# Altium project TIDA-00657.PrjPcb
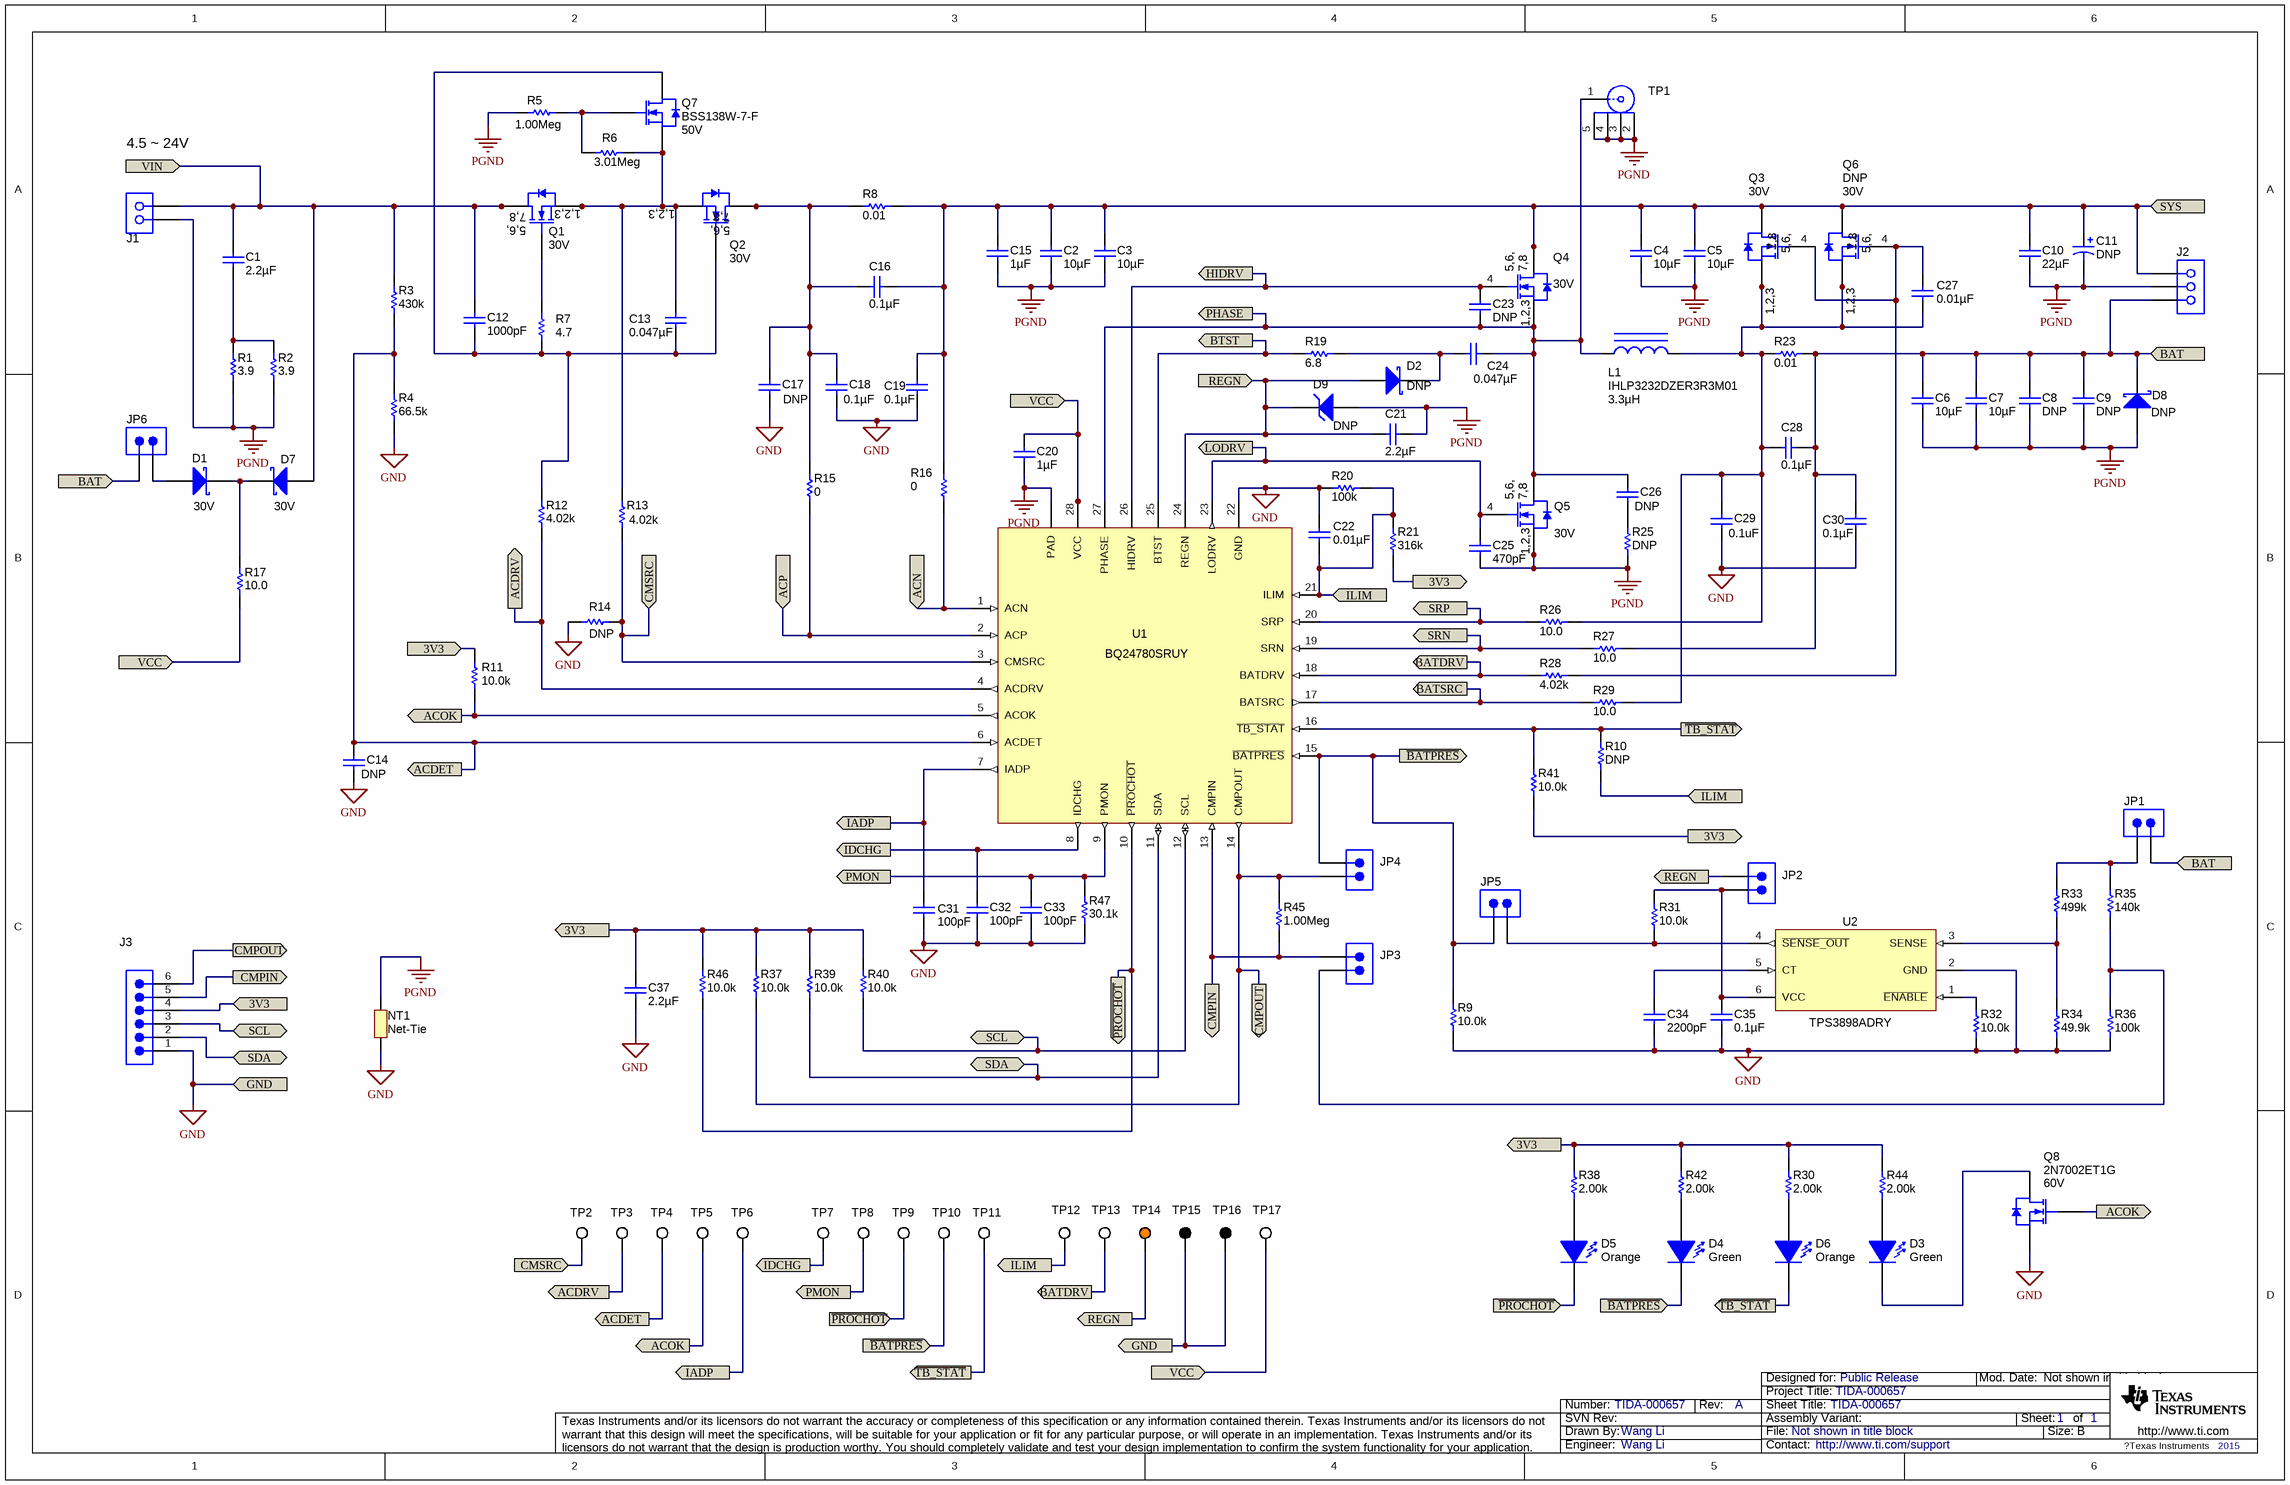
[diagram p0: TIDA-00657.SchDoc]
TechSupport: http://www.ti.com/support; SCH_Rev: A; PRJ_Title: TIDA-000657; PRJ_Number: TIDA-000657; PRJ_Engineer: Wang Li; PRJ_Customer: Public Release; PCB_Rev: B; PCB_Layout: Wang Li; CopyrightYear: 2015
2 sheets, 150 parts. Net scope: flat (ports and power ports of the same name join across sheets).
Board file: TIDA-00657.PcbDoc
Sheets:
  TIDA-00657.SchDoc
  TIDA-00657 Hardware_ANSI-B.SchDoc

## Sheet TIDA-00657.SchDoc: TIDA-000657
size 431 x 279 mm; Date: Not shown in title block; ApprovedBy: Not shown in title block; CheckedBy: Not shown in title block; Author: Not shown in title block; CompanyName: Not shown in title block; DrawnBy: Wang Li; Engineer: Wang Li; Organization: Not shown in title block; Address1: Not shown in title block; Address2: Not shown in title block; Address3: Not shown in title block; Address4: Not shown in title block; DocumentNumber: 1; Revision: A; SheetNumber: 1; SheetTotal: 1; PageSetup: Record=PageOptions¦CenterHorizontal=True¦CenterVertical=True¦PrintScale=0.62¦XCorrection=1.00¦YCorrection=1.00¦PrintKind=0¦BorderSize=5000000¦LeftOffset=0¦BottomOffset=0¦Orientation=2¦PaperLength=1000¦PaperWidth=1000¦Scale=100¦PaperSource=15¦PrintQuality=-3¦MediaType=1¦DitherType=10¦PrintScaleMode=1¦PaperKind=Letter¦PaperIndex=1

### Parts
C1  ValueDisplayed: 2.2µF  [1206]  (hidden comment: GRM31MR71E225KA93L)
C2  ValueDisplayed: 10µF  [1206]  (hidden comment: GRM31CR61E106KA12L)
C3  ValueDisplayed: 10µF  [1206]  (hidden comment: GRM31CR61E106KA12L)
C4  ValueDisplayed: 10µF  [1206]  (hidden comment: GRM31CR61E106KA12L)
C5  ValueDisplayed: 10µF  [1206]  (hidden comment: GRM31CR61E106KA12L)
C6  ValueDisplayed: 10µF  [1206]  (hidden comment: GRM31CR61E106KA12L)
C7  ValueDisplayed: 10µF  [1206]  (hidden comment: GRM31CR61E106KA12L)
C8  ValueDisplayed: DNP  [1206]  (hidden comment: GRM31CR61E106KA12L)
C9  ValueDisplayed: DNP  [1206]  (hidden comment: GRM31CR61E106KA12L)
C10  ValueDisplayed: 22µF  [1210]  (hidden comment: GRM32ER61E226KE15L)
C11  ValueDisplayed: DNP  [7343-28]  (hidden comment: 16TQC150MYF)
C12  ValueDisplayed: 1000pF  [0603]  (hidden comment: GRM188R71H102KA01D)
C13  ValueDisplayed: 0.047µF  [0603]  (hidden comment: GRM188R71H473KA61D)
C14  value DNP  [0603]  (hidden comment: GRM188R71E104KA01D)
C15  ValueDisplayed: 1µF  [0603]  (hidden comment: GRM188R71E105KA12D)
C16  ValueDisplayed: 0.1µF  [0603]  (hidden comment: GRM188R71E104KA01D)
C17  Value1: DNP  [0603]  (hidden comment: GRM188R71E105KA12D)
C18  ValueDisplayed: 0.1µF  [0603]  (hidden comment: GRM188R71E104KA01D)
C19  ValueDisplayed: 0.1µF  [0603]  (hidden comment: GRM188R71E104KA01D)
C20  ValueDisplayed: 1µF  [0603]  (hidden comment: GRM188R71E105KA12D)
C21  ValueDisplayed: 2.2µF  [0603]  (hidden comment: GRM188R61C225KE15D)
C22  ValueDisplayed: 0.01µF  [0603]  (hidden comment: C0603X103K5RACTU)
C23  ValueDisplayed: DNP  [0603]  (hidden comment: GRM188R71E104KA01D)
C24  ValueDisplayed: 0.047µF  [0603]  (hidden comment: GRM188R71H473KA61D)
C25  ValueDisplayed: 470pF  [0603]  (hidden comment: GRM188R71H471KA01D)
C26  value DNP  [0603]  (hidden comment: GRM188R71E104KA01D)
C27  ValueDisplayed: 0.01µF  [0603]  (hidden comment: C0603X103K5RACTU)
C28  ValueDisplayed: 0.1µF  [0603]  (hidden comment: GRM188R71E104KA01D)
C29  value 0.1uF  [0603]  (hidden comment: GRM188R71E104KA01D)
C30  ValueDisplayed: 0.1µF  [0603]  (hidden comment: GRM188R71E104KA01D)
C31  ValueDisplayed: 100pF  [0603]  (hidden comment: C0603C101J5GAC)
C32  ValueDisplayed: 100pF  [0603]  (hidden comment: C0603C101J5GAC)
C33  ValueDisplayed: 100pF  [0603]  (hidden comment: C0603C101J5GAC)
C34  ValueDisplayed: 2200pF  [0805_HV]  (hidden comment: C2012C0G1H222J)
C35  ValueDisplayed: 0.1µF  [0603]  (hidden comment: GRM188R71E104KA01D)
C37  ValueDisplayed: 2.2µF  [0603]  (hidden comment: GRM188R71A225KE15D)
D1  value 30V  [sod-323]  (hidden comment: BAT54HT1G)
D2  value DNP  [sod-323]  (hidden comment: BAT54HT1G)
D3  value Green  [LED_LTST-C190]  (hidden comment: LTST-C190GKT)
D4  value Green  [LED_LTST-C190]  (hidden comment: LTST-C190GKT)
D5  value Orange  [LED_LTST-C190]  (hidden comment: LTST-C190KFKT)
D6  value Orange  [LED_LTST-C190]  (hidden comment: LTST-C190KFKT)
D7  value 30V  [sod-323]  (hidden comment: BAT54HT1G)
D8  value DNP  [SMA]  (hidden comment: SS12-E3/61T)
D9  Vz_V: DNP  [SOD-123]  (hidden comment: BZT52C8V2-7-F)
J1  ED120/2DS  [CONN_ED120-2DS]  (value not drawn)
J2  ED120/3DS  [CONN_ED120_3DS]  (value not drawn)
J3  ED555/6DS  [TERM_BLK_ED555-6DS]  (value not drawn)
JP1  5-146261-1  [CONN_5-146261-1]  (value not drawn)
JP2  5-146261-1  [CONN_5-146261-1]  (value not drawn)
JP3  5-146261-1  [CONN_5-146261-1]  (value not drawn)
JP4  5-146261-1  [CONN_5-146261-1]  (value not drawn)
JP5  5-146261-1  [CONN_5-146261-1]  (value not drawn)
JP6  5-146261-1  [CONN_5-146261-1]  (value not drawn)
L1  IHLP3232DZER3R3M01  ValueDisplayed: 3.3µH  [IHLP-3232DZ]
NT1  Net-Tie  [Net-Tie_20milWide_60milLong]  (net tie, no BOM)
Q1  value 30V  [TRANS_NexFET_Q3]  (hidden comment: CSD17308Q3)
Q2  value 30V  [TRANS_NexFET_Q3]  (hidden comment: CSD17308Q3)
Q3  value 30V  [TRANS_NexFET_Q3]  (hidden comment: CSD17308Q3)
Q4  value 30V  [TRANS_NexFET_Q3]  (hidden comment: CSD17308Q3)
Q5  value 30V  [TRANS_NexFET_Q3]  (hidden comment: CSD17308Q3)
Q6  DNP  value 30V  [TRANS_NexFET_Q3]
Q7  BSS138W-7-F  value 50V  [SOT-323]
Q8  2N7002ET1G  value 60V  [SOT-23]
R1  value 3.9  [1210M]  (hidden comment: ERJ-14YJ3R9U)
R2  value 3.9  [1210M]  (hidden comment: ERJ-14YJ3R9U)
R3  value 430k  [0603]  (hidden comment: RC0603FR-07430KL)
R4  value 66.5k  [0603]  (hidden comment: CRCW060366K5FKEA)
R5  value 1.00Meg  [0603]  (hidden comment: CRCW06031M00FKEA)
R6  value 3.01Meg  [0603]  (hidden comment: CRCW06033M01FKEA)
R7  value 4.7  [0603]  (hidden comment: CRCW06034R70JNEA)
R8  value 0.01  [1206]  (hidden comment: WSLP1206R0100FEA)
R9  value 10.0k  [0603]  (hidden comment: CRCW060310K0FKEA)
R10  value DNP  [0603]  (hidden comment: RG1608P-8452-B-T5)
R11  value 10.0k  [0603]  (hidden comment: CRCW060310K0FKEA)
R12  value 4.02k  [0603]  (hidden comment: CRCW06034K02FKEA)
R13  value 4.02k  [0603]  (hidden comment: CRCW06034K02FKEA)
R14  value DNP  [0603]  (hidden comment: CRCW06030000Z0EA)
R15  value 0  [0603]  (hidden comment: CRCW06030000Z0EA)
R16  value 0  [0603]  (hidden comment: CRCW06030000Z0EA)
R17  value 10.0  [1206]  (hidden comment: ERJ-8ENF10R0V)
R19  value 6.8  [0603]  (hidden comment: CRCW06036R80JNEA)
R20  value 100k  [0603]  (hidden comment: CRCW0603100KJNEA)
R21  value 316k  [0603]  (hidden comment: CRCW0603316KFKEA)
R23  value 0.01  [1206]  (hidden comment: WSLP1206R0100FEA)
R25  value DNP  [0603]  (hidden comment: CRCW0603100KFKEA)
R26  value 10.0  [0603]  (hidden comment: RC0603FR-0710RL)
R27  value 10.0  [0603]  (hidden comment: RC0603FR-0710RL)
R28  value 4.02k  [0603]  (hidden comment: CRCW06034K02FKEA)
R29  value 10.0  [0603]  (hidden comment: RC0603FR-0710RL)
R30  value 2.00k  [0603]  (hidden comment: CRCW06032K00FKEA)
R31  value 10.0k  [0603]  (hidden comment: CRCW060310K0FKEA)
R32  value 10.0k  [0603]  (hidden comment: CRCW060310K0FKEA)
R33  value 499k  [0603]  (hidden comment: CRCW0603499KFKEA)
R34  value 49.9k  [0603]  (hidden comment: CRCW060349K9FKEA)
R35  value 140k  [0603]  (hidden comment: CRCW0603140KFKEA)
R36  value 100k  [0603]  (hidden comment: CRCW0603100KJNEA)
R37  value 10.0k  [0603]  (hidden comment: CRCW060310K0FKEA)
R38  value 2.00k  [0603]  (hidden comment: CRCW06032K00FKEA)
R39  value 10.0k  [0603]  (hidden comment: CRCW060310K0FKEA)
R40  value 10.0k  [0603]  (hidden comment: CRCW060310K0FKEA)
R41  value 10.0k  [0603]  (hidden comment: CRCW060310K0FKEA)
R42  value 2.00k  [0603]  (hidden comment: CRCW06032K00FKEA)
R44  value 2.00k  [0603]  (hidden comment: CRCW06032K00FKEA)
R45  value 1.00Meg  [0603]  (hidden comment: CRCW06031M00FKEA)
R46  value 10.0k  [0603]  (hidden comment: CRCW060310K0FKEA)
R47  value 30.1k  [0603]  (hidden comment: CRCW060330K1FKEA)
TP1  131-5031-00  [Tek_131-5031-00]  (value not drawn)
TP2  5002  [Keystone5002]  (value not drawn)
TP3  5002  [Keystone5002]  (value not drawn)
TP4  5002  [Keystone5002]  (value not drawn)
TP5  5002  [Keystone5002]  (value not drawn)
TP6  5002  [Keystone5002]  (value not drawn)
TP7  5002  [Keystone5002]  (value not drawn)
TP8  5002  [Keystone5002]  (value not drawn)
TP9  5002  [Keystone5002]  (value not drawn)
TP10  5002  [Keystone5002]  (value not drawn)
TP11  5002  [Keystone5002]  (value not drawn)
TP12  5002  [Keystone5002]  (value not drawn)
TP13  5002  [Keystone5002]  (value not drawn)
TP14  5003  [Keystone5003]  (value not drawn)
TP15  5001  [Keystone5001]  (value not drawn)
TP16  5001  [Keystone5001]  (value not drawn)
TP17  5002  [Keystone5002]  (value not drawn)
U1  BQ24780SRUY  [RUY0028A]
U2  TPS3898ADRY  [DRY0006A]

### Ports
3V3, 3V3 (in), ACDET, ACDRV (out), ACN (in), ACOK (out), ACP (in), BAT, BATDRV (out), BATSRC (out), BTST, CMPIN, CMPOUT (out), CMSRC, GND, HIDRV, IADP (out), IDCHG (out), ILIM, LODRV (out), PHASE, PMON (out), REGN, SCL (bidir), SDA (bidir), SRN, SRP, SYS, VCC, VIN, ~{BATPRES}, ~{PROCHOT}, ~{TB_STAT} (out)

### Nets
GND: C14.2 C17.2 C18.2 C19.2 C22.1 C29.2 C30.2 C31.2 C32.2 C33.2 C34.1 C35.1 C37.2 J3.1 NT1.1 Q8.2(S) R4.1 R9.2 R14.2 R20.2 R32.2 R34.1 R36.1 R47.2 TP15.1 TP16.1 U1.22(GND) U2.2(GND) ; port GND
PGND: C2.2 C3.2 C4.2 C5.2 C6.2 C7.2 C8.2 C9.2 C10.2 C11.2(-) C15.2 C20.2 C21.2 C25.2 D8.2(A) D9.2(A) J1.2 J2.2 NT1.2 Q5.1(S) Q5.2(S) Q5.3(S) R1.1 R2.1 R5.1 R25.1 TP1.2 TP1.3 TP1.4 TP1.5 U1.29(PAD)
3V3: C37.1 J3.4 R11.2 R21.1 R30.1 R37.2 R38.1 R39.2 R40.1 R41.2 R42.1 R44.1 R46.2 ; port 3V3
~{BATPRES}: D4.2(K) JP4.1 JP5.1 R9.1 TP10.1 U1.15(~{BATPRES}) ; port ~{BATPRES}
~{PROCHOT}: D5.2(K) R46.1 TP9.1 U1.10(~{PROCHOT}) ; port ~{PROCHOT}
~{TB_STAT}: D6.2(K) R10.2 R41.1 TP11.1 U1.16(~{TB_STAT}) ; port ~{TB_STAT}
ACDET: C14.1 R3.1 R4.2 TP4.1 U1.6(ACDET) ; port ACDET
ACDRV: R12.1 TP3.1 U1.4(ACDRV) ; port ACDRV
ACN: R16.1 U1.1(ACN) ; port ACN
ACOK: Q8.1(G) R11.1 TP5.1 U1.5(ACOK) ; port ACOK
ACP: R15.1 U1.2(ACP) ; port ACP
BAT: C6.1 C7.1 C8.1 C9.1 C28.2 C30.1 D8.1(K) J2.1 JP1.1 JP6.2 R23.2 R27.2 ; port BAT
BATDRV: R28.2 TP13.1 U1.18(BATDRV) ; port BATDRV
BATSRC: R29.1 U1.17(BATSRC) ; port BATSRC
BTST: R19.1 U1.25(BTST) ; port BTST
CMPIN: J3.5 JP3.1 R45.1 U1.13(CMPIN) ; port CMPIN
CMPOUT: J3.6 JP4.2 R37.1 R45.2 U1.14(CMPOUT) ; port CMPOUT
CMSRC: R13.1 R14.1 TP2.1 U1.3(CMSRC) ; port CMSRC
HIDRV: C23.1 Q4.4(G) U1.26(HIDRV) ; port HIDRV
IADP: C31.1 TP6.1 U1.7(IADP) ; port IADP
IDCHG: C32.1 TP7.1 U1.8(IDCHG) ; port IDCHG
ILIM: C22.2 R10.1 R20.1 R21.2 TP12.1 U1.21(ILIM) ; port ILIM
LODRV: C25.1 Q5.4(G) U1.23(LODRV) ; port LODRV
PHASE: C23.2 C24.2 C26.1 L1.1 Q4.1(S) Q4.2(S) Q4.3(S) Q5.5(D) Q5.6(D) Q5.7(D) Q5.8(D) TP1.1 U1.27(PHASE) ; port PHASE
PMON: C33.1 R47.1 TP8.1 U1.9(PMON) ; port PMON
REGN: C21.1 D2.2(A) D9.1(K) JP2.1 TP14.1 U1.24(REGN) ; port REGN
SCL: J3.3 R40.2 U1.12(SCL) ; port SCL
SDA: J3.2 R39.1 U1.11(SDA) ; port SDA
SRN: R27.1 U1.19(SRN) ; port SRN
SRP: R26.1 U1.20(SRP) ; port SRP
SYS: C2.1 C3.1 C4.1 C5.1 C10.1 C11.1(+) C15.1 C16.2 C19.1 J2.3 Q3.5(D) Q3.6(D) Q3.7(D) Q3.8(D) Q4.5(D) Q4.6(D) Q4.7(D) Q4.8(D) Q6.5(D) Q6.6(D) Q6.7(D) Q6.8(D) R8.2 R16.2 ; port SYS
VCC: C20.1 R17.1 TP17.1 U1.28(VCC) ; port VCC
VIN: C1.1 C12.1 D7.2(A) J1.1 Q1.5(D) Q1.6(D) Q1.7(D) Q1.8(D) R3.2 ; port VIN
NetC1_2: C1.2 R1.2 R2.2
NetC12_2: C12.2 C13.2 Q2.4(G) Q7.3(D) R7.1 R12.2
NetC13_1: C13.1 Q1.1(S) Q1.2(S) Q1.3(S) Q2.1(S) Q2.2(S) Q2.3(S) Q7.2(S) R6.2 R13.2
NetC16_1: C16.1 C17.1 C18.1 Q2.5(D) Q2.6(D) Q2.7(D) Q2.8(D) R8.1 R15.2
NetC24_1: C24.1 D2.1(K) R19.2
NetC26_2: C26.2 R25.2
NetC27_1: C27.1 Q3.4(G) Q6.4(G) R28.1
NetC27_2: C27.2 C28.1 C29.1 L1.2 Q3.1(S) Q3.2(S) Q3.3(S) Q6.1(S) Q6.2(S) Q6.3(S) R23.1 R26.2 R29.2
NetC34_2: C34.2 U2.5(CT)
NetC35_2: C35.2 JP2.2 R31.1 U2.6(VCC)
NetD1_1: D1.1(K) D7.1(K) R17.2
NetD1_2: D1.2(A) JP6.1
NetD3_1: D3.1(A) R44.2
NetD3_2: D3.2(K) Q8.3(D)
NetD4_1: D4.1(A) R42.2
NetD5_1: D5.1(A) R38.2
NetD6_1: D6.1(A) R30.2
NetJP1_2: JP1.2 R33.2 R35.2
NetJP3_2: JP3.2 R35.1 R36.2
NetJP5_2: JP5.2 R31.2 U2.4(~{SENSE_OUT})
NetQ1_4: Q1.4(G) R7.2
NetQ7_1: Q7.1(G) R5.2 R6.1
NetR32_1: R32.1 U2.1(~{ENABLE})
NetR33_1: R33.1 R34.2 U2.3(SENSE)

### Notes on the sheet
- 4.5 ~ 24V

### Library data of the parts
C1 = GRM31MR71E225KA93L: CAP, CERM, 2.2uF, 25V, +/-10%, X7R, 1206; Manufacturer: MuRata; Polarized: N; CompType: Capacitor; U/M: EA; Cap_F: 0.0000022; Tolerance_%: 10; Value1: Unknown; VDC_V: 25; TaMin_C: -55; TaMax_C: 125; Cap_Case: 1210
C2-C9 = GRM31CR61E106KA12L: CAP, CERM, 10uF, 25V, +/-10%, X5R, 1206; Manufacturer: MuRata; Polarized: N; CompType: Capacitor; U/M: EA; Cap_F: 0.00001; Tolerance_%: 10; ESR_Ohm: 0.004; Value1: 0.004 ohm; VDC_V: 25; TaMin_C: -55; TaMax_C: 85
C10 = GRM32ER61E226KE15L: CAP, CERM, 22uF, 25V, +/-10%, X5R, 1210; Manufacturer: MuRata; Polarized: N; CompType: Capacitor; U/M: EA; Cap_F: 0.000022; Tolerance_%: 10; ESR_Ohm: 0.002; Value1: 0.002 ohm; VDC_V: 25; IRMS_A: 3.67; TaMin_C: -55; TaMax_C: 85
C11 = 16TQC150MYF: CAP, TA, 150uF, 16V, +/-20%, 0.05 ohm, SMD; Manufacturer: Panasonic; Polarized: Y; CompType: Capacitor; U/M: EA; Cap_F: 0.00015; Tolerance_%: 20; VDC_V: 16; ESR_Ohm: 0.05; IRMS_A: 1.8; TaMin_C: -55; TaMax_C: 105; Cap_Case: 7.3x2.8x4.3
C12 = GRM188R71H102KA01D: CAP, CERM, 1000pF, 50V, +/-10%, X7R, 0603; Manufacturer: MuRata; Polarized: N; CompType: Capacitor; U/M: EA; Cap_F: 0.000000001; Tolerance_%: 10; Value1: Unknown; VDC_V: 50; TaMin_C: -55; TaMax_C: 125
C13 C24 = GRM188R71H473KA61D: CAP, CERM, 0.047uF, 50V, +/-10%, X7R, 0603; Manufacturer: MuRata; Polarized: N; CompType: Capacitor; U/M: EA; Cap_F: 0.000000047; Tolerance_%: 10; Value1: Unknown; VDC_V: 50; TaMin_C: -55; TaMax_C: 125
C14 C16 C18 C19 C23 C26 C28-C30 C35 = GRM188R71E104KA01D: CAP, CERM, 0.1uF, 25V, +/-10%, X7R, 0603; Manufacturer: MuRata; Polarized: N; CompType: Capacitor; U/M: EA; Cap_F: 0.0000001; Tolerance_%: 10; Value1: Unknown; VDC_V: 25; TaMin_C: -55; TaMax_C: 125
C15 C20 = GRM188R71E105KA12D: CAP, CERM, 1uF, 25V, +/-10%, X7R, 0603; Manufacturer: MuRata; Polarized: N; CompType: Capacitor; U/M: EA; Cap_F: 0.000001; Tolerance_%: 10; Value1: Unknown; VDC_V: 25; TaMin_C: -55; TaMax_C: 125
C17 = GRM188R71E105KA12D: CAP, CERM, 1uF, 25V, +/-10%, X7R, 0603; Manufacturer: MuRata; Polarized: N; CompType: Capacitor; U/M: EA; Cap_F: 0.000001; Tolerance_%: 10; VDC_V: 25; TaMin_C: -55; TaMax_C: 125
C21 = GRM188R61C225KE15D: CAP, CERM, 2.2uF, 16V, +/-10%, X5R, 0603; Manufacturer: MuRata; Polarized: N; CompType: Capacitor; U/M: EA; Cap_F: 0.0000022; Tolerance_%: 10; Value1: Unknown; VDC_V: 16; TaMin_C: -55; TaMax_C: 85
C22 C27 = C0603X103K5RACTU: CAP, CERM, 0.01uF, 50V, +/-10%, X7R, 0603; Manufacturer: Kemet; Polarized: N; CompType: Capacitor; U/M: EA; Cap_F: 0.00000001; Tolerance_%: 10; Value1: Unknown; VDC_V: 50; TaMin_C: -55; TaMax_C: 125
C25 = GRM188R71H471KA01D: CAP, CERM, 470pF, 50V, +/-10%, X7R, 0603; Manufacturer: MuRata; Polarized: N; CompType: Capacitor; U/M: EA; Cap_F: 0.00000000047; Tolerance_%: 10; Value1: Unknown; VDC_V: 50; TaMin_C: -55; TaMax_C: 125
C31-C33 = C0603C101J5GAC: CAP, CERM, 100pF, 50V, +/-5%, C0G/NP0, 0603; Manufacturer: Kemet; Polarized: N; CompType: Capacitor; U/M: EA; Cap_F: 0.0000000001; Tolerance_%: 5; Value1: Unknown; VDC_V: 50; TaMin_C: -55; TaMax_C: 125
C34 = C2012C0G1H222J: CAP, CERM, 2200pF, 50V, +/-5%, C0G/NP0, 0805; Manufacturer: TDK; Polarized: N; CompType: Capacitor; U/M: EA; Cap_F: 0.0000000022; Tolerance_%: 5; Value1: Unknown; VDC_V: 50; TaMin_C: -55; TaMax_C: 125; Cap_Case: 0805
C37 = GRM188R71A225KE15D: CAP, CERM, 2.2uF, 10V, +/-10%, X7R, 0603; Manufacturer: MuRata; Polarized: N; CompType: Capacitor; U/M: EA; Cap_F: 0.0000022; Tolerance_%: 10; ESR_Ohm: 0.009; Value1: 0.009 ohm; TaMin_C: -55; TaMax_C: 125
D1 D2 D7 = BAT54HT1G: Diode, Schottky, 30V, 0.2A, SOD-323; Manufacturer: ON Semiconductor; U/M: EA; Vf_V: 0.35; Value2: 0.35V; Io_A: 0.2; Vr_V: 30
D3 D4 = LTST-C190GKT: LED, Green, SMD; Manufacturer: Lite-On; Vf_V: 2.1; Value2: 2.1V; Io_A: 0.02; Power_TotalModule: 0.1; Value1: 0.1W; U/M: EA
D5 D6 = LTST-C190KFKT: LED, Orange, SMD; Manufacturer: Lite-On; Type: AlInGaP; Vf_V: 2; Value2: 2V; Io_A: 0.02; Power_TotalModule: 0.075; Value1: 0.075W; U/M: EA
D8 = SS12-E3/61T: Diode, Schottky, 20V, 1A, SMA; Manufacturer: Vishay-Semiconductor; U/M: EA; Vf_V: 0.5; Value2: 0.5V; Io_A: 1; Vr_V: 20; TJmax_C: 125; RJC_CperW: 28
D9 = BZT52C8V2-7-F: Diode, Zener, 8.2V, 500mW, SOD-123; Manufacturer: Diodes Inc.; SymbolCreator: a0412235; U/M: EA; Power_W: 0.5; Value1: 0.5W; RJA_CperW: 338
J1 = ED120/2DS: TERMINAL BLOCK 5.08MM VERT 2POS; Manufacturer: On-Shore Technology, Inc.; U/M: EA
J2 = ED120/3DS: TERMINAL BLOCK 5.08MM VERT 3POS; Manufacturer: On-Shore Technology, Inc.; SymbolCreator: a0412235; U/M: EA
J3 = ED555/6DS: Terminal Block, 6A, 3.5mm Pitch, 6-Pos, TH; Manufacturer: On-Shore Technology, Inc.; SymbolCreator: a0412235; CompType: Connector; U/M: EA
JP1-JP6 = 5-146261-1: Header, 100mil, 2x1, Gold plated, TH; Manufacturer: TE Connectivity; SymbolCreator: a0412235; U/M: EA
L1 = IHLP3232DZER3R3M01: Inductor, Shielded, Powdered Iron, 3.3uH, 9.2A, 17.7 ohm, SMD; Manufacturer: Vishay-Dale; Ind_H: 3.3E-6; Imax_A: 9.2; Irms: 9.2A @ 40C rise; Isat: 20A @ 20% inductance drop; DCR_ohm: 17.7; U/M: EA
NT1 = Net-Tie: Single point connection between nets.; SymbolCreator: codlsc
Q1-Q6 = CSD17308Q3: MOSFET, N-CH, 30V, 47A, SON 3.3x3.3mm; Manufacturer: Texas Instruments; Alternate Manufacturer: None; U/M: EA; ChType: N; VdsMax_V: 30; Value1: 0.0094 ohm; Rdson45_Ohm: 0.0094; Value2: 3.9 nC; QgTyp_nC: 3.9; Vgs_V: 10; IdsMax_A: 47
Q7 = BSS138W-7-F: MOSFET, N-CH, 50V, 0.2A, SOT-323; Manufacturer: Diodes Inc.; Alternate Manufacturer: None; U/M: EA; ChType: N; VdsMax_V: 50; Value1: 3.5 ohm; Rdson45_Ohm: 3.5; Value2: ? nC; Vgs_V: 1.5; IdsMax_A: 0.2
Q8 = 2N7002ET1G: MOSFET, N-CH, 60V, 0.26A, SOT-23; Manufacturer: ON Semiconductor; Alternate Manufacturer: None; U/M: EA; ChType: N; VdsMax_V: 60; Value1: 3 ohm; Rdson45_Ohm: 3; Value2: 0.81 nC; QgTyp_nC: 0.81; Vgs_V: 20; IdsMax_A: 0.26
R1 R2 = ERJ-14YJ3R9U: RES, 3.9 ohm, 5%, 0.5W, 1210; Manufacturer: Panasonic; CompType: Resistor; Value_Code: 3R90; Tolerance_%: 5; Power_W: 0.5; VDC_V: 200; TempCo: 600 ppm/C; EIA_Code: E24; U/M: EA
R3 = RC0603FR-07430KL: RES, 430k ohm, 1%, 0.1W, 0603; Manufacturer: Yageo America; CompType: Resistor; Res_ohm: 430000; Tolerance_%: 1; Power_W: 0.1; VDC_V: 150; TempCo: 200 ppm/C; U/M: EA
R4 = CRCW060366K5FKEA: RES, 66.5k ohm, 1%, 0.1W, 0603; Manufacturer: Vishay-Dale; CompType: Resistor; Res_ohm: 66500; Value_Code: 66k5; Tolerance_%: 1; Power_W: 0.1; VDC_V: 75; TempCo: 100 ppm/C; EIA_Code: E96; U/M: EA
R5 R45 = CRCW06031M00FKEA: RES, 1.00Meg ohm, 1%, 0.1W, 0603; Manufacturer: Vishay-Dale; CompType: Resistor; Res_ohm: 1000000; Value_Code: 1M00; Tolerance_%: 1; Power_W: 0.1; VDC_V: 75; TempCo: 100 ppm/C; EIA_Code: E96; U/M: EA
R6 = CRCW06033M01FKEA: RES, 3.01Meg ohm, 1%, 0.1W, 0603; Manufacturer: Vishay-Dale; CompType: Resistor; Res_ohm: 3010000; Value_Code: 3M01; Tolerance_%: 1; Power_W: 0.1; VDC_V: 75; TempCo: 100 ppm/C; EIA_Code: E96; U/M: EA
R7 = CRCW06034R70JNEA: RES, 4.7 ohm, 5%, 0.1W, 0603; Manufacturer: Vishay-Dale; CompType: Resistor; Value_Code: 4R70; Tolerance_%: 5; Power_W: 0.1; VDC_V: 75; TempCo: 200 ppm/C; EIA_Code: E24; U/M: EA
R8 R23 = WSLP1206R0100FEA: RES, 0.01 ohm, 1%, 1W, 1206; Manufacturer: Vishay-Dale; CompType: Resistor; Value_Code: R010; Tolerance_%: 1; TempCo: 75 ppm/C; EIA_Code: E96; U/M: EA
R9 R11 R31 R32 R37 R39-R41 R46 = CRCW060310K0FKEA: RES, 10.0k ohm, 1%, 0.1W, 0603; Manufacturer: Vishay-Dale; CompType: Resistor; Res_ohm: 10000; Value_Code: 10k0; Tolerance_%: 1; Power_W: 0.1; VDC_V: 75; TempCo: 100 ppm/C; EIA_Code: E96; U/M: EA
R10 = RG1608P-8452-B-T5: RES, 84.5k ohm, 0.1%, 0.1W, 0603; Manufacturer: Susumu Co Ltd; CompType: Resistor; Res_ohm: 84500; Value_Code: 84k5; Tolerance_%: 0.1; VDC_V: 75; TempCo: 25 ppm/C; EIA_Code: E192; U/M: EA
R12 R13 R28 = CRCW06034K02FKEA: RES, 4.02k ohm, 1%, 0.1W, 0603; Manufacturer: Vishay-Dale; CompType: Resistor; Res_ohm: 4020; Value_Code: 4k02; Tolerance_%: 1; Power_W: 0.1; VDC_V: 75; TempCo: 100 ppm/C; EIA_Code: E96; U/M: EA
R14 = CRCW06030000Z0EA: RES, 0 ohm, 5%, 0.1W, 0603; Manufacturer: Vishay-Dale; CompType: Resistor; Res_ohm: 0; Value_Code: 0000; Tolerance_%: 5; Power_W: 0.1; VDC_V: 75; TempCo: 200 ppm/C; EIA_Code: E24; U/M: EA
R15 R16 = CRCW06030000Z0EA: RES, 0 ohm, 5%, 0.1W, 0603; Manufacturer: Vishay-Dale; CompType: Resistor; Value_Code: 0000; Tolerance_%: 5; Power_W: 0.1; VDC_V: 75; TempCo: 200 ppm/C; EIA_Code: E24; U/M: EA
R17 = ERJ-8ENF10R0V: RES, 10.0 ohm, 1%, 0.25W, 1206; Manufacturer: Panasonic; CompType: Resistor; Res_ohm: 10; Value_Code: 10R0; Tolerance_%: 1; Power_W: 0.25; VDC_V: 200; TempCo: 100 ppm/C; EIA_Code: E96; U/M: EA
R19 = CRCW06036R80JNEA: RES, 6.8 ohm, 5%, 0.1W, 0603; Manufacturer: Vishay-Dale; CompType: Resistor; Value_Code: 6R80; Tolerance_%: 5; Power_W: 0.1; VDC_V: 75; TempCo: 200 ppm/C; EIA_Code: E24; U/M: EA
R20 R36 = CRCW0603100KJNEA: RES, 100k ohm, 5%, 0.1W, 0603; Manufacturer: Vishay-Dale; CompType: Resistor; Res_ohm: 100000; Tolerance_%: 5; Power_W: 0.1; VDC_V: 75; TempCo: 200 ppm/C; EIA_Code: E24; U/M: EA
R21 = CRCW0603316KFKEA: RES, 316k ohm, 1%, 0.1W, 0603; Manufacturer: Vishay-Dale; CompType: Resistor; Res_ohm: 316000; Tolerance_%: 1; Power_W: 0.1; VDC_V: 75; TempCo: 100 ppm/C; EIA_Code: E96; U/M: EA
R25 = CRCW0603100KFKEA: RES, 100k ohm, 1%, 0.1W, 0603; Manufacturer: Vishay-Dale; CompType: Resistor; Res_ohm: 100000; Tolerance_%: 1; Power_W: 0.1; VDC_V: 75; TempCo: 100 ppm/C; EIA_Code: E96; U/M: EA
R26 R27 R29 = RC0603FR-0710RL: RES, 10.0 ohm, 1%, 0.1W, 0603; Manufacturer: Yageo America; CompType: Resistor; Res_ohm: 10; Value_Code: 10R0; Tolerance_%: 1; Power_W: 0.1; VDC_V: 150; TempCo: 200 ppm/C; EIA_Code: E96; U/M: EA
R30 R38 R42 R44 = CRCW06032K00FKEA: RES, 2.00k ohm, 1%, 0.1W, 0603; Manufacturer: Vishay-Dale; CompType: Resistor; Res_ohm: 2000; Value_Code: 2k00; Tolerance_%: 1; Power_W: 0.1; VDC_V: 75; TempCo: 100 ppm/C; EIA_Code: E96; U/M: EA
R33 = CRCW0603499KFKEA: RES, 499k ohm, 1%, 0.1W, 0603; Manufacturer: Vishay-Dale; CompType: Resistor; Res_ohm: 499000; Tolerance_%: 1; Power_W: 0.1; VDC_V: 75; TempCo: 100 ppm/C; EIA_Code: E96; U/M: EA
R34 = CRCW060349K9FKEA: RES, 49.9k ohm, 1%, 0.1W, 0603; Manufacturer: Vishay-Dale; CompType: Resistor; Res_ohm: 49900; Value_Code: 49k9; Tolerance_%: 1; Power_W: 0.1; VDC_V: 75; TempCo: 100 ppm/C; EIA_Code: E96; U/M: EA
R35 = CRCW0603140KFKEA: RES, 140k ohm, 1%, 0.1W, 0603; Manufacturer: Vishay-Dale; CompType: Resistor; Res_ohm: 140000; Tolerance_%: 1; Power_W: 0.1; VDC_V: 75; TempCo: 100 ppm/C; EIA_Code: E96; U/M: EA
R47 = CRCW060330K1FKEA: RES, 30.1k ohm, 1%, 0.1W, 0603; Manufacturer: Vishay-Dale; CompType: Resistor; Res_ohm: 30100; Value_Code: 30k1; Tolerance_%: 1; Power_W: 0.1; VDC_V: 75; TempCo: 100 ppm/C; EIA_Code: E96; U/M: EA
TP1 = 131-5031-00: Compact Probe Tip Circuit Board Test Points, TH, 25 per; Manufacturer: Tektronix; U/M: EA
TP2-TP13 TP17 = 5002: Test Point, TH, Miniature, White; Manufacturer: Keystone; CompType: Test Point Loop; U/M: EA
TP14 = 5003: Test Point, Miniature, Orange, TH; Manufacturer: Keystone; CompType: Test Point Loop; U/M: EA
TP15 TP16 = 5001: Test Point, Miniature, Black, TH; Manufacturer: Keystone; CompType: Test Point Loop; U/M: EA
U1 = BQ24780RUY: 1-4 Cell Turbo Boost Mode Battery Charge Controller with Power Monitoring and /PROCHOT for CPU Throttling, RUY0028A; Alternate Manufacturer: None; Manufacturer: Texas Instruments; SymbolCreator: a04799628; CompType: IC; U/M: EA
U2 = TPS3898ADRY: Single-Channel, Adjustable Supervisory Circuit in Ultra-Small Package, DRY0006A; Alternate Manufacturer: None; Manufacturer: Texas Instruments; SymbolCreator: a0411947; CompType: IC; U/M: EA

## Sheet TIDA-00657 Hardware_ANSI-B.SchDoc
size 431 x 279 mm; Date: Not shown in title block; ApprovedBy: Not shown in title block; CheckedBy: Not shown in title block; Author: Not shown in title block; CompanyName: Not shown in title block; Engineer: Not shown in title block; Organization: Not shown in title block; Address1: Not shown in title block; Address2: Not shown in title block; Address3: Not shown in title block; Address4: Not shown in title block; DocumentNumber: 1; Revision: Use project parameter SCH_Rev; SheetNumber: 3; SheetTotal: 3; PageSetup: Record=PageOptions¦CenterHorizontal=True¦CenterVertical=True¦PrintScale=1.00¦XCorrection=1.00¦YCorrection=1.00¦PrintKind=0¦BorderSize=5000000¦LeftOffset=0¦BottomOffset=0¦Orientation=2¦PaperLength=1000¦PaperWidth=1000¦Scale=100¦PaperSource=15¦PrintQuality=600¦MediaType=1¦DitherType=10¦PaperKind=Letter¦PrintScaleMode=1
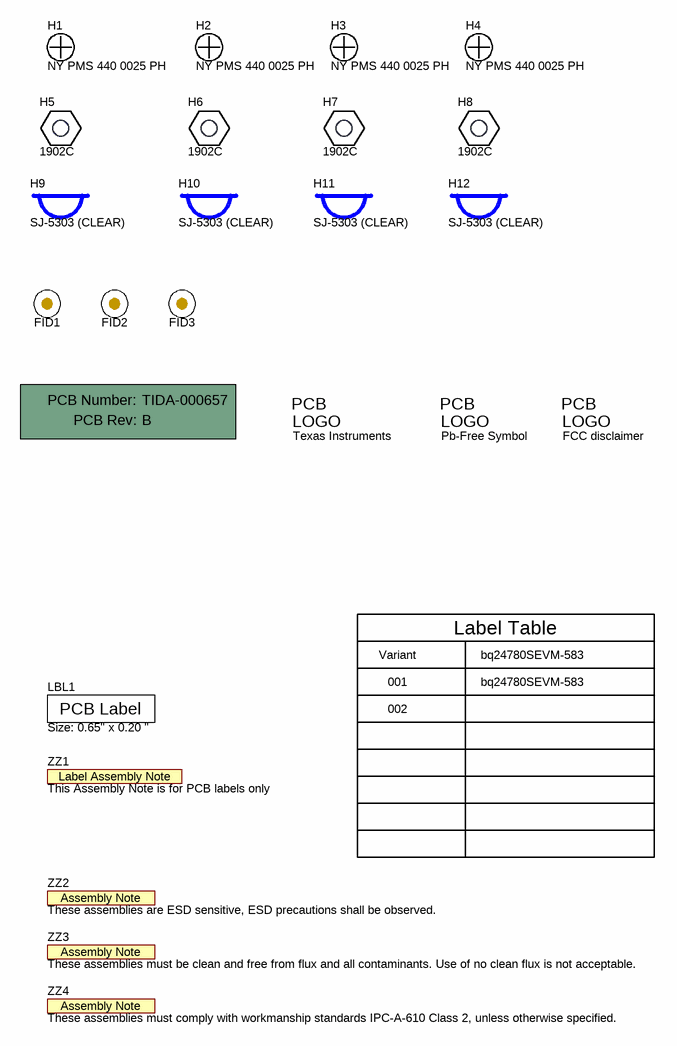
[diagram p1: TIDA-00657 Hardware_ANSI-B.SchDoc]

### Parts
!PCB  Printed Circuit Board  (value not drawn)  (mechanical)
FID1  Fiducial  [Fiducial10-20]  (value not drawn)
FID2  Fiducial  [Fiducial10-20]  (value not drawn)
FID3  Fiducial  [Fiducial10-20]  (value not drawn)
H1  NY PMS 440 0025 PH  [NY PMS 440 0025 PH]
H2  NY PMS 440 0025 PH  [NY PMS 440 0025 PH]
H3  NY PMS 440 0025 PH  [NY PMS 440 0025 PH]
H4  NY PMS 440 0025 PH  [NY PMS 440 0025 PH]
H5  1902C  [Keystone_1902C]
H6  1902C  [Keystone_1902C]
H7  1902C  [Keystone_1902C]
H8  1902C  [Keystone_1902C]
H9  SJ-5303 (CLEAR)  [Bumpon_SJ5003Transparent]
H10  SJ-5303 (CLEAR)  [Bumpon_SJ5003Transparent]
H11  SJ-5303 (CLEAR)  [Bumpon_SJ5003Transparent]
H12  SJ-5303 (CLEAR)  [Bumpon_SJ5003Transparent]
LBL1  Size: 0.65" x 0.20 "  [Label_650x200]
Logo1  Texas Instruments  [TI_Stacked_Overlay_Small]  (no BOM)
Logo2  Pb-Free Symbol  [Pb-Free_Overlay_Small]  (no BOM)
Logo3  FCC disclaimer  [FCC_disclaimer_stacked]  (no BOM)
ZZ1  This Assembly Note is for PCB labels only  [AssemblyNoteLabel]  (no BOM)
ZZ2  These assemblies are ESD sensitive, ESD precautions shall be observed.  [AssemblyNote]  (no BOM)
ZZ3  These assemblies must be clean and free from flux and all contaminants. Use of no clean flux is not acceptable.  [AssemblyNote]  (no BOM)
ZZ4  These assemblies must comply with workmanship standards IPC-A-610 Class 2, unless otherwise specified.  [AssemblyNote]  (no BOM)

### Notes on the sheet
- Variant
- Label Table
- bq24780SEVM-583
- 001
- 002

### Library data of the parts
!PCB = PCB: Manufacturer: Any; PartNumber: TIDA-000657; SymbolCreator: a0412235
FID1-FID3 = Fiducial: Fiducial mark.  There is nothing to buy or mount.; SymbolCreator: codlsc
H1-H4 = NY PMS 440 0025 PH: Machine Screw, Round, #4-40 x 1/4, Nylon, Philips panhead; Manufacturer: B&F Fastener Supply; CompType: Hardware; SymbolCreator: codlsc; U/M: EA
H5-H8 = 1902C: Standoff, Hex, 0.5"L #4-40 Nylon; Manufacturer: Keystone; CompType: Hardware
H9-H12 = SJ-5303 (CLEAR): Bumpon, Hemisphere, 0.44 X 0.20, Clear; Manufacturer: 3M; SymbolCreator: a0412235
LBL1 = THT-14-423-10: Thermal Transfer Printable Labels, 0.650" W x 0.200" H - 10,000 per roll; Manufacturer: Brady; SymbolCreator: a0412235; CompType: Label
Logo1 = TI_Logo: Texas Instrument Corporate Signature; SymbolCreator: codlsc
Logo2 = Pb-Free: SymbolCreator: a0412235
Logo3 = FCC_disclaimer: SymbolCreator: codlsc
ZZ1 = AssemblyNoteLabel: SymbolCreator: a0412235
ZZ2-ZZ4 = AssemblyNote: SymbolCreator: codlsc

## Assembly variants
001: not fitted C8 C9 C11 C14 C17 C23 C26 C33 D2 D8 D9 FID1 FID2 FID3 H1 H2 H3 H4 H5 H6 H7 H8 Q6 R10 R14 R25 TP1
